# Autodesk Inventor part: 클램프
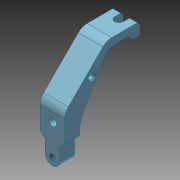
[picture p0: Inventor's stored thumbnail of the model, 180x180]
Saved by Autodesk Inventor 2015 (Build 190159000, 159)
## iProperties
Created: 2023-11
Part Number: 클램프
Material: 강철, 합금
Document SubType Name: Modeling
Designer: mdu-01
Density: 1 g/cm^3
Appearance: 기본값(1)
Author: mdu-01
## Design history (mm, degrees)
sketch "스케치1"
  geometry: L1 (0, 0)-(37.858, 0); L2 (44.929, -2.929)-(73.071, -31.071); L3 (76, -38.142)-(76, -59); L4 (74, -61)-(67, -61); L5 (66, -60)-(66, -56); L6 (67, -55)-(69, -55); L7 (70, -54)-(70, -40.868); L8 (65, -32.207)-(36.962, -16.019); L9 (21.962, -12)-(0, -12); L10 (0, -12)-(0, 0); L11 (66, -49.956)-(66, -66.044) reference; L12 (76, -59)-(74, -61); L13 (29.771, -17)-(32.23, -17) reference; L14 (31, -17)-(31, 0); L15 (6, -17.549)-(6, 0); C1 r 2 at (56, -22); A1 r 1 centre (67, -56) between (67, -55) and (66, -56); A2 r 1 centre (67, -60) between (66, -60) and (67, -61); A3 r 1 centre (69, -54) between (69, -55) and (70, -54); A4 r 10 centre (60, -40.868) between (70, -40.868) and (65, -32.207); A5 r 30 centre (21.962, -42) between (36.962, -16.019) and (21.962, -12); A6 r 10 centre (37.858, -10) between (44.929, -2.929) and (37.858, 0); A7 r 10 centre (66, -38.142) between (76, -38.142) and (73.071, -31.071); A8 r 6 centre (6, -17.549) between (10, -13.076) and (2, -13.076) reference; 4 further points
  constraints: 26 end point, 16 point on circle, 14 tangent, 9 centre point, 8 point on line, 5 parallel, 3 midpoint, 3 perpendicular, 2 horizontal, 1 equal radius, 4 other
  dimensions: "d0" = 12 distance between parallel lines of L1 L9; "d3" = 6 distance between parallel lines of L7 L3; "d4" = 10 distance between parallel lines of L5 L3; "d6" = 150 deg angle of L9 L8; "d7" = 30 distance from line of point (30, -12) L10; "d8" = 45 deg angle of L2 L1; "d9" = 42 distance of L1.start point (42, 0); "d10" = 6 distance between parallel lines of L6 L4; "d11" = 4 diameter of C1; "d12" = 22 distance from line of C1.centre L1; "d13" = 56 distance from line of C1.centre L10; "d14" = 1 radius of A1; "d15" = 61 distance between parallel lines of L4 L1 (derived); "d16" = 1 radius of A3; "d17" = 2 distance of L3.end point (76, -61); "d18" = 2 distance of L4.start point (76, -61) (= d17); "d19" = 10 radius of A4; "d20" = 30 radius of A5; "d21" = 10 radius of A6; "d22" = 10 radius of A7; "d23" = 6 distance between parallel lines of L15 L10 (derived); "d24" = 25 distance between parallel lines of L14 L15 (derived)
extrude "돌출1" new body sketch "스케치1" stored distance "d25" = 20; taper "d26" = 0 deg
sketch "스케치2"
  geometry: L1 (0, -21.962)-(20, -21.962) reference; L2 (0, -21.962)-(0, -1.962); L3 (0, -1.962)-(4, -5.962); L4 (4, -5.962)-(4, -21.962); L5 (10, -21.962)-(10, 6.53); L6 (20, -21.962)-(20, -1.962); L7 (20, -1.962)-(16, -5.962); L8 (16, -5.962)-(16, -21.962); L9 (0, -21.962)-(4, -21.962); L10 (16, -21.962)-(20, -21.962)
  constraints: 18 end point, 3 symmetric about line, 2 collinear, 2 perpendicular, 1 point on line, 1 vertical
  dimensions: "d27" = 45 deg angle of L2 L3; "d28" = 12 distance between parallel lines of L8 L4; "d30" = 20 distance from line of L2.end L1
extrude "돌출2" cut sketch "스케치2" stored distance "d31" = 20; taper "d32" = 0 deg
fillet "모깎기1"
chamfer "모따기1" distance "d33" = 1; stored, may be unused: second distance "d34" = 2, angle "d35" = 45 deg
hole "구멍1" diameter "d38" = 4.917; stored, may be unused: countersink angle "d42" = 90 deg, drill point angle "d44" = 118 deg; dims "d39" = 6, "d40" = 7, "d41" = 4, "d43" = 8, "d47" = 10, "d48" = 10
sketch "스케치3"
  geometry: C1 r 2.75 at (10, -6.858) reference; 1 further point
hole "구멍2" sketch "스케치3" at (10, -6.858) diameter "d45" = 4; stored, may be unused: countersink angle "d51" = 90 deg, drill point angle "d53" = 118 deg; dims "d46" = 6, "d49" = 6.5, "d50" = 8, "d52" = 8
sketch "스케치4"
  geometry: L1 (20, 22.858)-(0, 22.858) reference; L2 (20, 15.858)-(0, 15.858) reference; L3 (6.5, 15.858)-(6.5, 22.858); L4 (13.5, 15.858)-(13.5, 22.858); C1 r 2.5 at (10, 19.858) reference; A1 r 3.5 centre (10, 15.858) between (6.5, 15.858) and (13.5, 15.858); 1 further point
  constraints: 4 end point, 3 point on line, 2 perpendicular, 2 point on circle, 2 tangent, 1 centre point, 1 midpoint
  dimensions: "d57" = 7 diameter of A1
extrude "돌출3" cut sketch "스케치4" stored distance "d55" = 20; taper "d56" = 0 deg
node "솔리드1"
node "참조1"
node "참조2"
node "참조3"
node "참조4"
